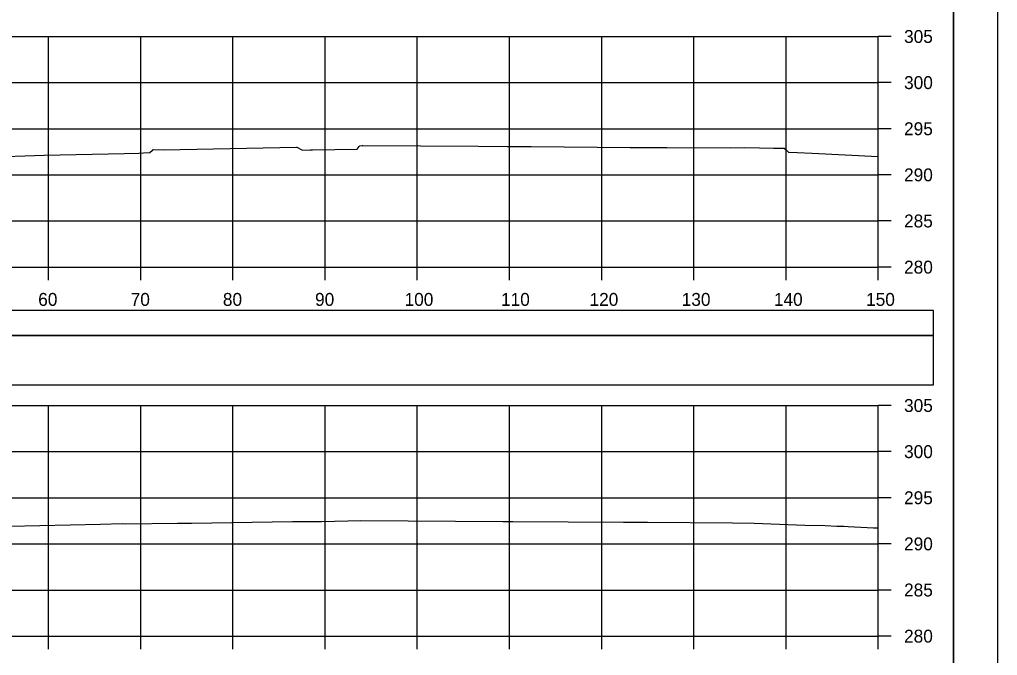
# Model space of a CAD drawing. Extents: x 1370538 to 1372872, y 376220 to 381127.
# Drawn here: x 1372765.5 to 1372871.6, y 376962.3 to 377031.3 of the extents above; entities that cross this region are included whole.
import ezdxf

# ---------------------------------------------------------------- set-up
doc = ezdxf.new("R2010")
doc.units = 0
for name, color, linetype in [('R_Border Notes', 7, 'Continuous'), ('R_Border PE', 7, 'Continuous'), ('R_Border Prem', 7, 'Continuous'), ('R_Dimension', 7, 'Continuous'), ('R_Grid', 7, 'Continuous'), ('R_No Plot', 7, 'Continuous'), ('T_Detection Zones', 7, 'Continuous')]:
    doc.layers.add(name, color=color, linetype=linetype)

msp = doc.modelspace()

# ---------------------------------------------------------------- linework, layer by layer
at = {"layer": 'R_Border Notes'}
msp.add_line((1372866.83, 376864.43), (1372866.83, 377069.89), dxfattribs=at)
at = {"layer": 'R_Border Prem'}
for p, q in [((1372858.65, 377004.43), (1372858.65, 377029.43)), ((1372860.05, 377029.43), (1372858.65, 377029.43)), ((1372860.05, 377024.43), (1372858.65, 377024.43)), ((1372860.05, 377019.43), (1372858.65, 377019.43)), ((1372860.05, 377014.43), (1372858.65, 377014.43)), ((1372860.05, 377009.43), (1372858.65, 377009.43)), ((1372558.65, 377004.43), (1372858.65, 377004.43)), ((1372768.65, 377003.03), (1372768.65, 377004.43)), ((1372778.65, 377003.03), (1372778.65, 377004.43)), ((1372788.65, 377003.03), (1372788.65, 377004.43)), ((1372798.65, 377003.03), (1372798.65, 377004.43)), ((1372808.65, 377003.03), (1372808.65, 377004.43)), ((1372818.65, 377003.03), (1372818.65, 377004.43)), ((1372828.65, 377003.03), (1372828.65, 377004.43)), ((1372838.65, 377003.03), (1372838.65, 377004.43)), ((1372848.65, 377003.03), (1372848.65, 377004.43)), ((1372858.65, 377003.03), (1372858.65, 377004.43)), ((1372860.05, 377004.43), (1372858.65, 377004.43)), ((1372858.65, 376964.43), (1372858.65, 376989.43)), ((1372860.05, 376989.43), (1372858.65, 376989.43)), ((1372860.05, 376984.43), (1372858.65, 376984.43)), ((1372860.05, 376979.43), (1372858.65, 376979.43)), ((1372860.05, 376974.43), (1372858.65, 376974.43)), ((1372860.05, 376969.43), (1372858.65, 376969.43)), ((1372558.65, 376964.43), (1372858.65, 376964.43)), ((1372768.65, 376963.03), (1372768.65, 376964.43)), ((1372778.65, 376963.03), (1372778.65, 376964.43)), ((1372788.65, 376963.03), (1372788.65, 376964.43)), ((1372798.65, 376963.03), (1372798.65, 376964.43)), ((1372808.65, 376963.03), (1372808.65, 376964.43)), ((1372818.65, 376963.03), (1372818.65, 376964.43)), ((1372828.65, 376963.03), (1372828.65, 376964.43)), ((1372838.65, 376963.03), (1372838.65, 376964.43)), ((1372848.65, 376963.03), (1372848.65, 376964.43)), ((1372858.65, 376963.03), (1372858.65, 376964.43)), ((1372860.05, 376964.43), (1372858.65, 376964.43))]:
    msp.add_line(p, q, dxfattribs=at)
at = {"layer": 'R_Dimension'}
for points in [[(1372755.48, 377016.13), (1372768.16, 377016.55), (1372776.88, 377016.74), (1372778.44, 377016.79), (1372778.96, 377016.83), (1372779.64, 377016.85), (1372779.92, 377017.1), (1372780, 377017.17), (1372780.05, 377017.17), (1372781.09, 377017.16), (1372782.94, 377017.19), (1372795.53, 377017.43), (1372795.56, 377017.43), (1372795.57, 377017.42), (1372795.58, 377017.42), (1372796.11, 377017.13), (1372797.08, 377017.12), (1372797.1, 377017.13), (1372797.27, 377017.13), (1372797.28, 377017.13), (1372802.12, 377017.22), (1372802.34, 377017.52), (1372802.41, 377017.59), (1372802.68, 377017.62), (1372802.75, 377017.63), (1372815.26, 377017.54), (1372818.44, 377017.52), (1372821, 377017.52), (1372831.74, 377017.38), (1372835.71, 377017.4), (1372842.65, 377017.35), (1372844.18, 377017.39), (1372845.76, 377017.37), (1372847.27, 377017.33), (1372847.92, 377017.31), (1372848.18, 377017.32), (1372848.43, 377017.33), (1372848.67, 377017.13), (1372848.92, 377016.9), (1372849.85, 377016.87), (1372851.47, 377016.8), (1372858.65, 377016.41)], [(1372761.08, 376976.28), (1372774.28, 376976.57), (1372776.62, 376976.63), (1372777.05, 376976.62), (1372782.63, 376976.69), (1372784.17, 376976.68), (1372795.1, 376976.84), (1372796.95, 376976.86), (1372798.27, 376976.85), (1372802.51, 376976.98), (1372817.92, 376976.86), (1372819.01, 376976.86), (1372831.02, 376976.79), (1372831.2, 376976.79), (1372831.36, 376976.79), (1372833.63, 376976.79), (1372842.84, 376976.72), (1372845.2, 376976.68), (1372850.67, 376976.47), (1372852.89, 376976.42), (1372854.16, 376976.36), (1372854.93, 376976.34), (1372855.4, 376976.32), (1372858.14, 376976.18), (1372858.65, 376976.17)]]:
    msp.add_lwpolyline(points, dxfattribs=at)
at = {"layer": 'R_Grid'}
for p, q in [((1372558.65, 377029.43), (1372858.65, 377029.43)), ((1372768.65, 377004.43), (1372768.65, 377029.43)), ((1372778.65, 377004.43), (1372778.65, 377029.43)), ((1372788.65, 377004.43), (1372788.65, 377029.43)), ((1372798.65, 377004.43), (1372798.65, 377029.43)), ((1372808.65, 377004.43), (1372808.65, 377029.43)), ((1372818.65, 377004.43), (1372818.65, 377029.43)), ((1372828.65, 377004.43), (1372828.65, 377029.43)), ((1372838.65, 377004.43), (1372838.65, 377029.43)), ((1372848.65, 377004.43), (1372848.65, 377029.43)), ((1372858.65, 377004.43), (1372858.65, 377029.43)), ((1372558.65, 377024.43), (1372858.65, 377024.43)), ((1372558.65, 377019.43), (1372858.65, 377019.43)), ((1372558.65, 377014.43), (1372858.65, 377014.43)), ((1372558.65, 377009.43), (1372858.65, 377009.43)), ((1372558.65, 377004.43), (1372858.65, 377004.43)), ((1372558.65, 376989.43), (1372858.65, 376989.43)), ((1372768.65, 376964.43), (1372768.65, 376989.43)), ((1372778.65, 376964.43), (1372778.65, 376989.43)), ((1372788.65, 376964.43), (1372788.65, 376989.43)), ((1372798.65, 376964.43), (1372798.65, 376989.43)), ((1372808.65, 376964.43), (1372808.65, 376989.43)), ((1372818.65, 376964.43), (1372818.65, 376989.43)), ((1372828.65, 376964.43), (1372828.65, 376989.43)), ((1372838.65, 376964.43), (1372838.65, 376989.43)), ((1372848.65, 376964.43), (1372848.65, 376989.43)), ((1372858.65, 376964.43), (1372858.65, 376989.43)), ((1372558.65, 376984.43), (1372858.65, 376984.43)), ((1372558.65, 376979.43), (1372858.65, 376979.43)), ((1372558.65, 376974.43), (1372858.65, 376974.43)), ((1372558.65, 376969.43), (1372858.65, 376969.43)), ((1372558.65, 376964.43), (1372858.65, 376964.43))]:
    msp.add_line(p, q, dxfattribs=at)
at = {"layer": 'R_No Plot'}
for points in [[(1372538.24, 377073.78), (1372871.58, 377073.78), (1372871.58, 376860.45), (1372538.24, 376860.45)], [(1372784.57, 377069.89), (1372784.57, 377060.01), (1372820.3, 377060.01), (1372820.3, 377057.09), (1372843.5, 377057.09), (1372843.5, 377032.76), (1372866.83, 377032.76), (1372866.83, 376864.43), (1372550.65, 376864.43), (1372550.65, 377069.89)]]:
    msp.add_lwpolyline(points, close=True, dxfattribs=at)
at = {"layer": 'T_Detection Zones'}
for points in [[(1372552.66, 376997), (1372864.63, 376997), (1372864.63, 376999.71), (1372552.66, 376999.71)], [(1372552.66, 376991.68), (1372864.63, 376991.68), (1372864.63, 376997), (1372552.66, 376997)]]:
    msp.add_lwpolyline(points, close=True, dxfattribs=at)

# ---------------------------------------------------------------- texts
at = {"layer": 'R_Border PE'}
for s, p in [('305', (1372861.45, 377028.73)), ('300', (1372861.45, 377023.73)), ('295', (1372861.45, 377018.73)), ('290', (1372861.45, 377013.73)), ('285', (1372861.45, 377008.73)), ('280', (1372861.45, 377003.73)), ('60', (1372767.53, 377000.23)), ('70', (1372777.56, 377000.23)), ('80', (1372787.56, 377000.23)), ('90', (1372797.56, 377000.23)), ('100', (1372807.27, 377000.23)), ('110', (1372817.73, 377000.23)), ('120', (1372827.33, 377000.23)), ('130', (1372837.33, 377000.23)), ('140', (1372847.33, 377000.23)), ('150', (1372857.33, 377000.23)), ('305', (1372861.45, 376988.73)), ('300', (1372861.45, 376983.73)), ('295', (1372861.45, 376978.73)), ('290', (1372861.45, 376973.73)), ('285', (1372861.45, 376968.73)), ('280', (1372861.45, 376963.73))]:
    msp.add_text(s, height=1.4, dxfattribs=at).set_placement(p)

doc.saveas('drawing.dxf')
